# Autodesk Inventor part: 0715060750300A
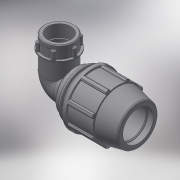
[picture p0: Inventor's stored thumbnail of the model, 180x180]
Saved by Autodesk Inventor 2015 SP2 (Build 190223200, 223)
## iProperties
Created: 2017-02
Part Number: 0715060750300A
Material: Generic
Description: PLASSON 90° ELBOW FEMALE ADAPTOR 75-3"
Document SubType Name: Modeling
Designer: KIM
Mass: 1287.77 g
Surface Area: 1760.4 cm^2
Volume: 1287.77 cm^3
Density: 1 g/cm^3
Appearance: Default
Author: KIM
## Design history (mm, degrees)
derived "87150.ipt"
feature "Solid1::87150.ipt"
tag "TaggingFeature1"
body "Solid1"
other parameters: "d2" = 75, "d4" = 15.91667, "d5" = 47.75, "d7" = 134, "d9" = 27.28571, "d11" = 4.775, "d13" = 120 deg, "d14" = 97.5, "d15" = 12 deg, "d16" = 125.96, "d18" = 3.75, "d19" = 35 deg, "d20" = 17.5 deg, "d21" = 124.62, "d23" = 0, "d25" = 360 deg, "d27" = 2.68, "d33" = 1.5, "d42" = 70.67, "d43" = 4.02, "d46" = 2.25, "d51" = 191, "d68" = 9.55, "d72" = 105, "d73" = 110.4038, "d74" = 36, "d75" = 126.96437, "d76" = 84.926, "d77" = 39.6, "d79" = 33.9704, "d80" = 2.54778, "d83" = 0, "d84" = 0, "d91" = 120.6, "d93" = 132, "d94" = 84.926, "d95" = 59.4482, "d96" = 9.55, "d97" = 50 deg, "d98" = 76.4334, "d99" = 0.5, "d100" = 0.5, "d101" = 12, "d102" = 110.4038, "d103" = 29.88, "d104" = 0, "d108" = 360 deg, "d110" = 2.07007, "d111" = 8.93333, "d112" = 0, "d113" = 2.3875, "d114" = 2.3875, "d115" = 122.1812, "d_" = 75, "E_" = 134, "A_" = 191, "l_" = 132, "l_2" = 36, "A_1" = 105, "Rp_" = 84.926, "d105" = 16.56057
